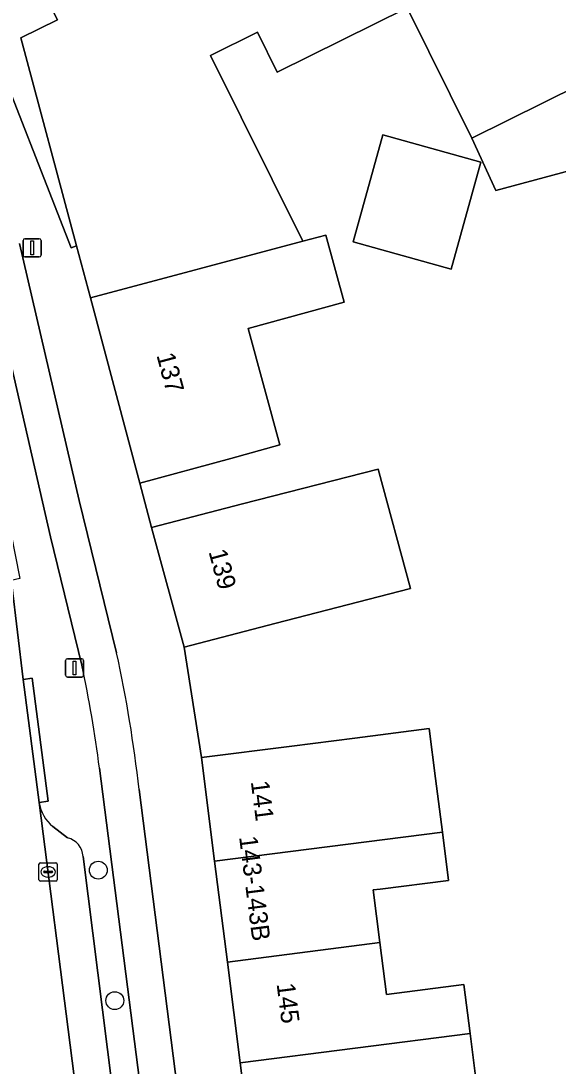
# Model space of a CAD drawing. Extents: x 162879 to 165540, y 384011 to 385181.
# Drawn here: x 164079.6 to 164109, y 384406.9 to 384464.1 of the extents above; entities that cross this region are included whole.
import ezdxf

# ---------------------------------------------------------------- set-up
doc = ezdxf.new("R2010")
doc.units = 0
for name, color, linetype in [('IMGEO_Boom', 7, 'Continuous'), ('IMGEO_Erf', 7, 'Continuous'), ('IMGEO_Fietspad_gesloten', 7, 'Continuous'), ('IMGEO_Kolk', 7, 'Continuous'), ('IMGEO_Lichtmast', 7, 'Continuous'), ('IMGEO_Pand', 7, 'Continuous'), ('IMGEO_Pand_nummerreeks', 7, 'Continuous'), ('IMGEO_Pand_overbouw', 7, 'Continuous'), ('IMGEO_Parkeervlak_open', 7, 'Continuous'), ('IMGEO_Rijbaan_lokaal_gesloten', 7, 'Continuous'), ('IMGEO_Rijbaan_lokaal_open', 7, 'Continuous'), ('IMGEO_Verkeerseiland_open', 7, 'Continuous'), ('IMGEO_Verkeersregelinstallatiepaal', 7, 'Continuous'), ('IMGEO_Voetpad_open', 7, 'Continuous')]:
    doc.layers.add(name, color=color, linetype=linetype)

msp = doc.modelspace()

# ---------------------------------------------------------------- linework, layer by layer
at = {"layer": 'IMGEO_Boom'}
for centre in [(164083.846, 384417.63), (164084.751, 384410.487)]:
    msp.add_circle(centre, 0.489, dxfattribs=at)
at = {"layer": 'IMGEO_Erf'}
msp.add_lwpolyline([(164120.011, 384458.704), (164105.63, 384454.833), (164104.315, 384457.699), (164100.767, 384464.846), (164093.655, 384461.316), (164092.565, 384463.51), (164089.995, 384462.234), (164095.046, 384452.059), (164096.319, 384452.398), (164097.326, 384448.725), (164092.057, 384447.281), (164093.802, 384440.913), (164091.108, 384440.174), (164086.127, 384438.809), (164086.771, 384436.397), (164091.74, 384437.684), (164099.183, 384439.592), (164100.96, 384433.052), (164093.523, 384431.128), (164088.544, 384429.83), (164089.493, 384423.793), (164094.453, 384424.426), (164097.894, 384424.865), (164101.977, 384425.386), (164102.327, 384422.644), (164102.701, 384419.711), (164103.038, 384417.073), (164099.298, 384416.596), (164098.903, 384416.546), (164099.271, 384413.664), (164099.634, 384410.819), (164103.883, 384411.362), (164104.225, 384408.684), (164104.56, 384406.054)], dxfattribs=at)
msp.add_lwpolyline([(164097.808, 384452.037), (164099.438, 384457.888), (164104.813, 384456.391), (164103.184, 384450.541)], close=True, dxfattribs=at)
at = {"layer": 'IMGEO_Fietspad_gesloten'}
for points in [[(164084.849, 384429.536), (164082.808, 384437.872), (164079.535, 384451.936)], [(164077.68, 384451.033), (164078.208, 384449.03), (164078.937, 384445.854), (164081.224, 384435.871), (164082.94, 384428.857)], [(164083.909, 384423.215), (164088.215, 384389.576), (164088.332, 384388.439), (164088.421, 384387.131), (164088.88, 384373.493), (164089.214, 384364.987), (164089.693, 384360.397), (164090.613, 384357.272), (164091.093, 384356.072)], [(164091.191, 384365.926), (164090.87, 384373.758), (164090.447, 384387.88), (164086.087, 384422.038)]]:
    msp.add_lwpolyline(points, dxfattribs=at)
for centre, radius, start, end in [((164011.581, 384413.587), 74.984, 6.47088, 12.28024), ((164020.81, 384415.282), 63.596, 7.16571, 12.32496)]:
    msp.add_arc(centre, radius, start, end, dxfattribs=at)
at = {"layer": 'IMGEO_Kolk'}
for p, q in [((164080.597, 384417.109), (164080.597, 384417.961)), ((164080.672, 384418.035), (164081.524, 384418.035)), ((164080.899, 384417.578), (164081.297, 384417.578)), ((164081.085, 384417.815), (164081.11, 384417.815)), ((164081.598, 384417.961), (164081.598, 384417.109)), ((164081.524, 384417.035), (164080.672, 384417.035)), ((164080.856, 384417.529), (164080.856, 384417.541)), ((164081.294, 384417.492), (164080.896, 384417.492)), ((164081.108, 384417.255), (164081.083, 384417.255)), ((164081.34, 384417.541), (164081.34, 384417.529))]:
    msp.add_line(p, q, dxfattribs=at)
for points in [[(164080.597, 384417.109), (164080.597, 384417.961)], [(164080.672, 384418.035), (164081.524, 384418.035)], [(164081.598, 384417.961), (164081.598, 384417.109)], [(164081.524, 384417.035), (164080.672, 384417.035)]]:
    msp.add_lwpolyline(points, dxfattribs=at)
for centre, radius, start, end in [((164080.674, 384417.959), 0.0765, 91.552, 178.448), ((164080.674, 384417.959), 0.0765, 91.552, 178.448), ((164080.896, 384417.538), 0.0403, 85.8775, 175.7526), ((164081.301, 384417.54), 0.0386, 1.7309, 96.639), ((164081.522, 384417.959), 0.0765, 1.552, 88.448), ((164081.522, 384417.959), 0.0765, 1.552, 88.448), ((164080.674, 384417.111), 0.0765, 181.552, 268.448), ((164080.674, 384417.111), 0.0765, 181.552, 268.448), ((164080.893, 384417.528), 0.0366, 178.938, 274.7102), ((164081.297, 384417.535), 0.043, 264.8664, 352.4533), ((164081.522, 384417.111), 0.0765, 271.552, 358.448), ((164081.522, 384417.111), 0.0765, 271.552, 358.448)]:
    msp.add_arc(centre, radius, start, end, dxfattribs=at)
for centre, major_axis, ratio, start_param, end_param in [((164081.084, 384417.535), (-0.387, 0.002), 0.722429, 4.712389, 7.853982), ((164081.109, 384417.535), (-0.39, 0.002), 0.717154, 1.570796, 4.712389)]:
    msp.add_ellipse(centre, major_axis=major_axis, ratio=ratio, start_param=start_param, end_param=end_param, dxfattribs=at)
at = {"layer": 'IMGEO_Lichtmast'}
for p, q in [((164082.054, 384428.305), (164082.054, 384429.105)), ((164082.054, 384429.105), (164082.054, 384428.305)), ((164082.154, 384429.205), (164082.944, 384429.205)), ((164082.944, 384429.205), (164082.154, 384429.205)), ((164083.044, 384429.105), (164083.044, 384428.305)), ((164083.044, 384428.305), (164083.044, 384429.105)), ((164082.944, 384428.205), (164082.154, 384428.205)), ((164082.154, 384428.205), (164082.944, 384428.205))]:
    msp.add_line(p, q, dxfattribs=at)
msp.add_lwpolyline([(164082.474, 384429.08), (164082.624, 384429.08), (164082.624, 384428.33), (164082.474, 384428.33), (164082.474, 384429.08)], dxfattribs=at)
for centre, start, end in [((164082.154, 384429.105), 90, 180), ((164082.154, 384429.105), 90, 180), ((164082.944, 384429.105), 0, 90), ((164082.944, 384429.105), 360, 90), ((164082.154, 384428.305), 180, 270), ((164082.154, 384428.305), 180, 270), ((164082.944, 384428.305), 270, 0), ((164082.944, 384428.305), 270, 0)]:
    msp.add_arc(centre, 0.1, start, end, dxfattribs=at)
at = {"layer": 'IMGEO_Pand'}
for points in [[(164095.246, 384476.092), (164100.767, 384464.846), (164104.315, 384457.699), (164116.14, 384463.569), (164110.825, 384474.323), (164109.759, 384473.791), (164106.025, 384481.355), (164105.235, 384481.061), (164103.422, 384480.161)], [(164095.046, 384452.059), (164089.995, 384462.234), (164092.565, 384463.51), (164093.655, 384461.316), (164100.767, 384464.846), (164095.246, 384476.092), (164090.203, 384473.589), (164090.286, 384473.393), (164084.202, 384468.608), (164081.227, 384466.269), (164081.4, 384465.909), (164080.878, 384465.649), (164081.604, 384464.184), (164079.608, 384463.197), (164082.653, 384451.818), (164083.416, 384448.962)], [(164103.184, 384450.541), (164104.813, 384456.391), (164099.438, 384457.888), (164097.808, 384452.037)], [(164095.046, 384452.059), (164083.416, 384448.962), (164086.127, 384438.809), (164091.108, 384440.174), (164093.802, 384440.913), (164092.057, 384447.281), (164097.326, 384448.725), (164096.319, 384452.398)], [(164099.183, 384439.592), (164091.74, 384437.684), (164086.771, 384436.397), (164088.544, 384429.83), (164093.523, 384431.128), (164100.96, 384433.052)], [(164090.217, 384418.12), (164102.701, 384419.711), (164102.327, 384422.644), (164101.977, 384425.386), (164097.894, 384424.865), (164094.453, 384424.426), (164089.493, 384423.793)], [(164098.903, 384416.546), (164099.298, 384416.596), (164103.038, 384417.073), (164102.701, 384419.711), (164090.217, 384418.12), (164090.922, 384412.599), (164099.271, 384413.664)], [(164103.883, 384411.362), (164099.634, 384410.819), (164099.271, 384413.664), (164090.922, 384412.599), (164091.626, 384407.078), (164104.225, 384408.684)], [(164091.626, 384407.078), (164092.35, 384401.409), (164095.489, 384401.81), (164097.31, 384402.042), (164100.742, 384402.48), (164100.354, 384405.517), (164104.56, 384406.054), (164104.225, 384408.684)]]:
    msp.add_lwpolyline(points, close=True, dxfattribs=at)
at = {"layer": 'IMGEO_Pand_overbouw'}
msp.add_lwpolyline([(164081.227, 384466.269), (164078.385, 384464.04), (164077.724, 384463.522), (164082.354, 384451.701), (164082.653, 384451.818), (164079.608, 384463.197), (164081.604, 384464.184), (164080.878, 384465.649), (164081.4, 384465.909)], close=True, dxfattribs=at)
at = {"layer": 'IMGEO_Parkeervlak_open'}
for points in [[(164080.607, 384421.336), (164085.705, 384381.473)], [(164082.161, 384419.402), (164081.358, 384420.022)], [(164087.267, 384384.65), (164083.012, 384418.373)]]:
    msp.add_lwpolyline(points, dxfattribs=at)
for centre, radius, start, end in [((164082.611, 384421.61), 2.022, 187.7752, 231.724), ((164081.897, 384418.317), 1.117, 2.8733, 76.3093)]:
    msp.add_arc(centre, radius, start, end, dxfattribs=at)
at = {"layer": 'IMGEO_Rijbaan_lokaal_gesloten'}
for points in [[(164080.607, 384421.336), (164079.729, 384428.073), (164079.105, 384433.247), (164079.067, 384433.494), (164078.32, 384437.198), (164077.922, 384438.514), (164069.399, 384435.394), (164070.192, 384433.183)], [(164080.489, 384372.432), (164080.558, 384368.374), (164087.023, 384368.952), (164086.558, 384373.446), (164086.427, 384375.821), (164085.739, 384381.108), (164085.705, 384381.473), (164080.607, 384421.336)]]:
    msp.add_lwpolyline(points, dxfattribs=at)
at = {"layer": 'IMGEO_Rijbaan_lokaal_open'}
msp.add_lwpolyline([(164119.047, 384466.705), (164117.994, 384466.52), (164112.445, 384477.691), (164109.594, 384483.138), (164106.025, 384481.355), (164109.759, 384473.791), (164110.825, 384474.323), (164116.14, 384463.569), (164104.315, 384457.699), (164105.63, 384454.833), (164120.011, 384458.704)], close=True, dxfattribs=at)
at = {"layer": 'IMGEO_Verkeerseiland_open'}
for points in [[(164082.94, 384428.857), (164081.224, 384435.871), (164078.937, 384445.854)], [(164077.922, 384438.514), (164078.32, 384437.198), (164078.81, 384437.296), (164079.557, 384433.592), (164079.067, 384433.494), (164079.105, 384433.247), (164079.729, 384428.073), (164080.224, 384428.137), (164081.102, 384421.4), (164080.607, 384421.336)], [(164085.705, 384381.473), (164085.739, 384381.108), (164086.234, 384381.172), (164086.922, 384375.885), (164086.427, 384375.821), (164086.558, 384373.446), (164087.023, 384368.952), (164087.16, 384367.013), (164087.325, 384364.879), (164089.214, 384364.987), (164088.88, 384373.493), (164088.421, 384387.131), (164088.332, 384388.439), (164088.215, 384389.576), (164083.909, 384423.215)], [(164081.358, 384420.022), (164082.161, 384419.402)], [(164083.012, 384418.373), (164087.267, 384384.65)]]:
    msp.add_lwpolyline(points, dxfattribs=at)
for centre, radius, start, end in [((164020.81, 384415.282), 63.596, 7.16571, 12.32496), ((164082.611, 384421.61), 2.022, 187.7752, 231.724), ((164081.897, 384418.317), 1.117, 2.8733, 76.3093)]:
    msp.add_arc(centre, radius, start, end, dxfattribs=at)
at = {"layer": 'IMGEO_Verkeersregelinstallatiepaal'}
for p, q in [((164079.725, 384451.302), (164079.725, 384452.102)), ((164079.725, 384452.102), (164079.725, 384451.302)), ((164079.825, 384452.202), (164080.615, 384452.202)), ((164080.615, 384452.202), (164079.825, 384452.202)), ((164080.715, 384452.102), (164080.715, 384451.302)), ((164080.715, 384451.302), (164080.715, 384452.102)), ((164080.615, 384451.202), (164079.825, 384451.202)), ((164079.825, 384451.202), (164080.615, 384451.202))]:
    msp.add_line(p, q, dxfattribs=at)
msp.add_lwpolyline([(164080.145, 384452.077), (164080.295, 384452.077), (164080.295, 384451.327), (164080.145, 384451.327), (164080.145, 384452.077)], dxfattribs=at)
for centre, start, end in [((164079.825, 384452.102), 90, 180), ((164079.825, 384452.102), 90, 180), ((164080.615, 384452.102), 0, 90), ((164080.615, 384452.102), 360, 90), ((164079.825, 384451.302), 180, 270), ((164079.825, 384451.302), 180, 270), ((164080.615, 384451.302), 270, 0), ((164080.615, 384451.302), 270, 0)]:
    msp.add_arc(centre, 0.1, start, end, dxfattribs=at)
at = {"layer": 'IMGEO_Voetpad_open'}
for points in [[(164081.227, 384466.269), (164078.385, 384464.04), (164077.724, 384463.522), (164082.354, 384451.701), (164082.653, 384451.818), (164079.608, 384463.197), (164081.604, 384464.184), (164080.878, 384465.649), (164081.4, 384465.909)], [(164080.607, 384421.336), (164081.102, 384421.4), (164080.224, 384428.137), (164079.729, 384428.073)]]:
    msp.add_lwpolyline(points, close=True, dxfattribs=at)
for points in [[(164083.416, 384448.962), (164082.653, 384451.818), (164082.354, 384451.701), (164077.724, 384463.522), (164075.268, 384466.013), (164074.538, 384465.159)], [(164079.535, 384451.936), (164082.808, 384437.872), (164084.849, 384429.536)], [(164092.471, 384358.045), (164098.816, 384360.506), (164098.233, 384361.24), (164096.843, 384367.207), (164093.334, 384367.41), (164093.863, 384376.535), (164094.394, 384385.679), (164094.662, 384390.073), (164095.062, 384396.637), (164095.127, 384397.422), (164092.895, 384397.137), (164092.35, 384401.409), (164091.626, 384407.078), (164090.922, 384412.599), (164090.217, 384418.12), (164089.493, 384423.793), (164088.544, 384429.83), (164086.771, 384436.397), (164086.127, 384438.809), (164083.416, 384448.962)], [(164086.087, 384422.038), (164090.447, 384387.88), (164090.87, 384373.758), (164091.191, 384365.926)]]:
    msp.add_lwpolyline(points, dxfattribs=at)
msp.add_arc((164011.581, 384413.587), 74.984, 6.47088, 12.28024, dxfattribs=at)

# ---------------------------------------------------------------- texts
at = {"layer": 'IMGEO_Pand_nummerreeks'}
for s, rotation, p in [('137', 284.9883, (164087.028, 384445.824)), ('139', 285.2167, (164089.882, 384435.063)), ('141', 277.2737, (164092.202, 384422.477)), ('143-143B', 277.2764, (164091.56, 384419.449)), ('145', 277.2764, (164093.615, 384411.398))]:
    msp.add_text(s, height=1, rotation=rotation, dxfattribs=at).set_placement(p)

doc.saveas('drawing.dxf')
